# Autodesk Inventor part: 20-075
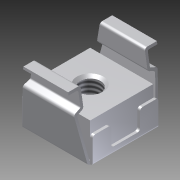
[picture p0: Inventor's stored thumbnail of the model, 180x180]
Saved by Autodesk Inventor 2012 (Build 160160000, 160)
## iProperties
Created: 2004-11
Part Number: 20-075
Document SubType Name: Modeling
Designer: Autodesk, Inc.
Manufacturer: Standard
Standards Organization: Custom
Description: CLIP NUT, M5 (#10-32)
Catalog Web Link: http://www.parker.com/ead/cm1.asp?cmid=809
Vendor: PARKER IPS
Mass: 1.10867 g
Surface Area: 14.9796 cm^2
Volume: 1.10867 cm^3
Density: 1 g/cm^3
Material: Default
CAGE: 1LJX3
Dept. ID: Product Design
Description #2: ---
Finish #1: ---
Finish #2: ---
Material ID: ---
Project Number: ---
Description: Clip Nut
Order Number: 20-075
Selection: Clip Nut
Supplier: Parker Hannifin Corp., Industrial Profile Systems Div.
Author: Autodesk, Inc.
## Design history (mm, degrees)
feature "Base1"
delete_face "Delete Face1"
patch "Boundary Patch1"
patch "Boundary Patch2"
feature "Stitch Surface1" dims "d9" = 0.254 (derived)
sketch "Sketch3"
  geometry: C1 r 2.75 at (6.25, 6.256) reference
hole "Hole1" sketch "Sketch3" at (6.25, 6.256) diameter "d2" = 3.9624; stored, may be unused: countersink angle "d6" = 82 deg, drill point angle "d8" = 118 deg; dims "d3" = 12.7, "d4" = 9.525, "d5" = 6.35, "d7" = 19.05
body "Solid1"
body "Srf1"
body "Srf2"
